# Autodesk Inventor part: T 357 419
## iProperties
Created: 2005-12
Part Number: T 357 419
Material: 2.0402.30
Document SubType Name: Modeling
Designer: I.Baliuc
Manufacturer: Standard
Standards Organization: Custom
Description: Federsockel
Density: 8.2 g/cm^3
Title: Federsockel
Company: Mayer & Müller AG Schaltgeräte
HalbzeugNorm: DIN 1761
Abmessung: Ms.Vkt 18
Author: T.Messerschmitt
Keywords: 382204
Revision Number: 357419
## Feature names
1. Extrusion2
2. Extrusion3
3. Bohrung_M5 [Hole]
4. Bohrung_M8 [Hole]
5. Drehung1 [Revolution]
